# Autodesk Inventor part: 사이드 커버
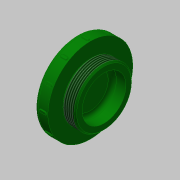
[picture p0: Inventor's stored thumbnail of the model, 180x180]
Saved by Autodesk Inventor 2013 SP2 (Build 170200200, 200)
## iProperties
Created: 2016-08
Part Number: 사이드 커버
Material: 스테인리스강
Document SubType Name: Modeling
Designer: mduedu
Density: 8.08 g/cm^3
Author: mduedu
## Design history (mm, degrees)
sketch "스케치1"
  geometry: L1 (-5, 0)-(5, 0); L2 (-5, 0)-(-5, 31); L3 (-5, 31)-(5, 31); L4 (5, 31)-(5, 21); L5 (5, 21)-(15, 21); L6 (15, 21)-(15, 16); L7 (15, 16)-(5, 16); L8 (5, 16)-(5, 0); 2 further points
  constraints: 16 end point, 4 parallel, 2 perpendicular, 1 coincident, 1 collinear, 1 horizontal, 1 midpoint, 1 vertical
  dimensions: "d0" = 10 distance of L1.start L1.end; "d2" = 62 diameter of L3 L1; "d3" = 42 diameter of L5 L1; "d4" = 10 distance between parallel lines of L6 L8; "d5" = 5 distance of L5.end L6.end
revolve "회전1" sketch "스케치1" stored, may be unused: angle "d6" = 90 deg
fillet "모깎기1" dims "d7" = 3
sketch "스케치2"
  geometry: L1 (5, -31)-(5, 31) reference; L2 (5, 21)-(15, 21) reference; L3 (0, 0)-(5, 0); L4 (5, 21)-(6, 21); L5 (6, 21)-(6, 20); L6 (6, 20)-(5, 20); L7 (5, 20)-(5, 21)
  constraints: 10 end point, 2 parallel, 1 horizontal, 1 midpoint, 1 perpendicular
  dimensions: "d8" = 1 distance of L2.start L4.end; "d9" = 40 diameter of L6 L3
revolve "회전2" sketch "스케치2" stored, may be unused: angle "d10" = 90 deg
fillet "모깎기2" dims "d11" = 3
feature "스레드1" dims "d12" = 10, "d13" = 0
chamfer "모따기1" distance "d14" = 1; stored, may be unused: second distance "d15" = 2, angle "d16" = 45 deg
node "작업 평면1"
sketch "스케치3"
  geometry: L1 (1, -1)-(-4, -1); L2 (-4, -1)-(-4, 1); L3 (-4, 1)-(1, 1); L4 (1, 1)-(1, -1); 2 further points
  constraints: 8 end point, 2 parallel, 1 horizontal, 1 horizontal alignment, 1 midpoint, 1 perpendicular
  dimensions: "d18" = 2 distance of L3.end L1.start; "d20" = 5 distance of L1.start L1.end; "d21" = 1 distance from line of L4 point (0, 0)
extrude "돌출1" join sketch "스케치3" stored distance "d22" = 10; taper "d23" = 0 deg
fillet "모깎기3" dims "d24" = 1
fillet "모깎기4" dims "d25" = 0.2
sketch "스케치4"
  geometry: 2 further points
  constraints: 1 coincident, 1 other
feature "엠보싱1" sketch "스케치4" dims "d0" = 10, "d2" = 62, "d3" = 42, "d4" = 10, "d5" = 5, "d29" = 0.5, "d30" = 0
node "솔리드1"
pattern_circular "원형 패턴1" dims "d27" = 360 deg
other parameters: "d17" = 31.5
